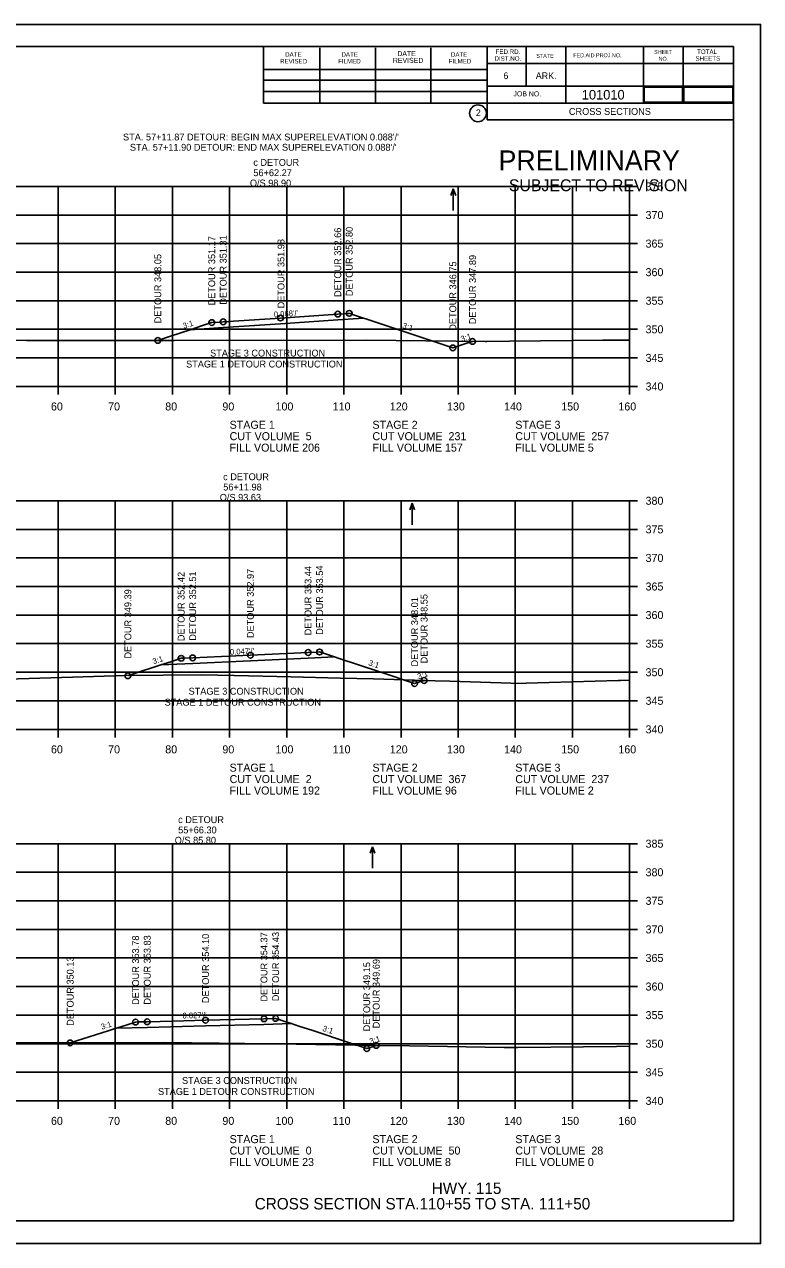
# Model space of a CAD drawing. Extents: x 1630712 to 1632516, y 782146 to 785403.
# Drawn here: x 1632387 to 1632515.9, y 784336.6 to 784550 of the extents above; entities that cross this region are included whole.
import ezdxf

# ---------------------------------------------------------------- set-up
doc = ezdxf.new("R2010")
doc.units = 0
for name, color, linetype in [('Notes', 7, 'Continuous'), ('Page Number', 7, 'Continuous'), ('R_Axis', 7, 'Continuous'), ('R_Axis Annot', 7, 'Continuous'), ('R_Border', 7, 'Continuous'), ('R_Border Notes', 7, 'Continuous'), ('R_Border Prem', 7, 'Continuous'), ('R_Detour Subgrade', 7, 'Continuous'), ('R_Detour Surface', 7, 'Continuous'), ('R_Draft', 7, 'Continuous'), ('R_Exist Surface', 7, 'Continuous'), ('R_Grid', 7, 'Continuous'), ('R_No Plot', 7, 'Continuous'), ('R_Water Annot', 7, 'Continuous'), ('R_Xsect Elev Detour', 7, 'Continuous'), ('R_Xsect Slope', 7, 'Continuous'), ('Total_Pages', 7, 'Continuous')]:
    doc.layers.add(name, color=color, linetype=linetype)

msp = doc.modelspace()

# ---------------------------------------------------------------- linework, layer by layer
at = {"layer": 'Page Number'}
msp.add_lwpolyline([(1632495.54, 784536.36), (1632502.21, 784536.36), (1632502.21, 784539), (1632495.54, 784539)], close=True, dxfattribs=at)
at = {"layer": 'R_Axis'}
for p, q in [((1632492.96, 784486.63), (1632492.96, 784521.63)), ((1632494.36, 784521.63), (1632492.96, 784521.63)), ((1632494.36, 784516.63), (1632492.96, 784516.63)), ((1632494.36, 784511.63), (1632492.96, 784511.63)), ((1632494.36, 784506.63), (1632492.96, 784506.63)), ((1632494.36, 784501.63), (1632492.96, 784501.63)), ((1632494.36, 784496.63), (1632492.96, 784496.63)), ((1632494.36, 784491.63), (1632492.96, 784491.63)), ((1632212.96, 784486.63), (1632492.96, 784486.63)), ((1632392.96, 784485.23), (1632392.96, 784486.63)), ((1632402.96, 784485.23), (1632402.96, 784486.63)), ((1632412.96, 784485.23), (1632412.96, 784486.63)), ((1632422.96, 784485.23), (1632422.96, 784486.63)), ((1632432.96, 784485.23), (1632432.96, 784486.63)), ((1632442.96, 784485.23), (1632442.96, 784486.63)), ((1632452.96, 784485.23), (1632452.96, 784486.63)), ((1632462.96, 784485.23), (1632462.96, 784486.63)), ((1632472.96, 784485.23), (1632472.96, 784486.63)), ((1632482.96, 784485.23), (1632482.96, 784486.63)), ((1632492.96, 784485.23), (1632492.96, 784486.63)), ((1632494.36, 784486.63), (1632492.96, 784486.63)), ((1632492.96, 784426.63), (1632492.96, 784466.63)), ((1632494.36, 784466.63), (1632492.96, 784466.63)), ((1632494.36, 784461.63), (1632492.96, 784461.63)), ((1632494.36, 784456.63), (1632492.96, 784456.63)), ((1632494.36, 784451.63), (1632492.96, 784451.63)), ((1632494.36, 784446.63), (1632492.96, 784446.63)), ((1632494.36, 784441.63), (1632492.96, 784441.63)), ((1632494.36, 784436.63), (1632492.96, 784436.63)), ((1632494.36, 784431.63), (1632492.96, 784431.63)), ((1632212.96, 784426.63), (1632492.96, 784426.63)), ((1632392.96, 784425.23), (1632392.96, 784426.63)), ((1632402.96, 784425.23), (1632402.96, 784426.63)), ((1632412.96, 784425.23), (1632412.96, 784426.63)), ((1632422.96, 784425.23), (1632422.96, 784426.63)), ((1632432.96, 784425.23), (1632432.96, 784426.63)), ((1632442.96, 784425.23), (1632442.96, 784426.63)), ((1632452.96, 784425.23), (1632452.96, 784426.63)), ((1632462.96, 784425.23), (1632462.96, 784426.63)), ((1632472.96, 784425.23), (1632472.96, 784426.63)), ((1632482.96, 784425.23), (1632482.96, 784426.63)), ((1632492.96, 784425.23), (1632492.96, 784426.63)), ((1632494.36, 784426.63), (1632492.96, 784426.63)), ((1632492.96, 784361.63), (1632492.96, 784406.63)), ((1632494.36, 784406.63), (1632492.96, 784406.63)), ((1632494.36, 784401.63), (1632492.96, 784401.63)), ((1632494.36, 784396.63), (1632492.96, 784396.63)), ((1632494.36, 784391.63), (1632492.96, 784391.63)), ((1632494.36, 784386.63), (1632492.96, 784386.63)), ((1632494.36, 784381.63), (1632492.96, 784381.63)), ((1632494.36, 784376.63), (1632492.96, 784376.63)), ((1632494.36, 784371.63), (1632492.96, 784371.63)), ((1632494.36, 784366.63), (1632492.96, 784366.63)), ((1632212.96, 784361.63), (1632492.96, 784361.63)), ((1632392.96, 784360.23), (1632392.96, 784361.63)), ((1632402.96, 784360.23), (1632402.96, 784361.63)), ((1632412.96, 784360.23), (1632412.96, 784361.63)), ((1632422.96, 784360.23), (1632422.96, 784361.63)), ((1632432.96, 784360.23), (1632432.96, 784361.63)), ((1632442.96, 784360.23), (1632442.96, 784361.63)), ((1632452.96, 784360.23), (1632452.96, 784361.63)), ((1632462.96, 784360.23), (1632462.96, 784361.63)), ((1632472.96, 784360.23), (1632472.96, 784361.63)), ((1632482.96, 784360.23), (1632482.96, 784361.63)), ((1632492.96, 784360.23), (1632492.96, 784361.63)), ((1632494.36, 784361.63), (1632492.96, 784361.63))]:
    msp.add_line(p, q, dxfattribs=at)
at = {"layer": 'R_Border'}
for p, q in [((1632194.96, 784546.09), (1632511.14, 784546.09)), ((1632428.88, 784536.21), (1632428.88, 784546.09)), ((1632438.74, 784536.21), (1632438.74, 784545.89)), ((1632448.5, 784536.21), (1632448.5, 784545.89)), ((1632458.18, 784536.21), (1632458.18, 784545.89)), ((1632468.04, 784546.09), (1632468.04, 784533.29)), ((1632474.88, 784546.09), (1632474.88, 784539.15)), ((1632481.82, 784546.09), (1632481.82, 784536.21)), ((1632495.4, 784546.09), (1632495.4, 784536.21)), ((1632502.34, 784546.09), (1632502.34, 784536.21)), ((1632511.14, 784340.63), (1632511.14, 784546.09)), ((1632511.14, 784543.15), (1632468.04, 784543.15)), ((1632511.14, 784543.17), (1632511.14, 784543.17)), ((1632428.88, 784542.07), (1632468.04, 784542.07)), ((1632428.88, 784540.21), (1632468.04, 784540.21)), ((1632511.14, 784539.15), (1632468.04, 784539.15)), ((1632471, 784539.15), (1632511.14, 784539.15)), ((1632428.88, 784536.21), (1632428.88, 784538.27)), ((1632428.88, 784538.27), (1632468.04, 784538.27)), ((1632511.14, 784536.21), (1632428.88, 784536.21)), ((1632468.04, 784533.29), (1632511.14, 784533.29)), ((1632511.14, 784340.63), (1632194.96, 784340.63))]:
    msp.add_line(p, q, dxfattribs=at)
msp.add_circle((1632466.43, 784534.43), 1.47, dxfattribs=at)
at = {"layer": 'R_Detour Subgrade'}
for points in [[(1632416.04, 784496.55), (1632421.84, 784496.94), (1632431.87, 784497.61), (1632441.89, 784498.29), (1632446.39, 784498.6)], [(1632410.92, 784437.9), (1632416.5, 784438.14), (1632426.6, 784438.6), (1632436.69, 784439.08), (1632441.34, 784439.3)], [(1632403.12, 784374.34), (1632408.55, 784374.47), (1632418.76, 784374.73), (1632428.98, 784375), (1632433.81, 784375.14)]]:
    msp.add_lwpolyline(points, dxfattribs=at)
at = {"layer": 'R_Detour Surface'}
for points in [[(1632410.4, 784494.68), (1632412.6, 784495.41), (1632416.04, 784496.55), (1632418.21, 784497.27), (1632419.84, 784497.81), (1632421.17, 784497.89), (1632421.84, 784497.94), (1632431.87, 784498.61), (1632431.87, 784498.61), (1632431.87, 784498.61), (1632431.87, 784498.61), (1632441.89, 784499.29), (1632443.79, 784499.42), (1632443.9, 784499.43), (1632444.46, 784499.24), (1632446.39, 784498.6), (1632446.4, 784498.6), (1632446.99, 784498.4), (1632459.74, 784494.15), (1632462.03, 784493.38), (1632464.81, 784494.3), (1632465.48, 784494.52)], [(1632405.19, 784436.03), (1632406.14, 784436.34), (1632410.92, 784437.9), (1632412.68, 784438.47), (1632414.48, 784439.06), (1632414.79, 784439.07), (1632416.5, 784439.14), (1632426.58, 784439.6), (1632426.6, 784439.6), (1632426.6, 784439.6), (1632436.69, 784440.08), (1632438.24, 784440.15), (1632438.71, 784440.17), (1632439.38, 784439.95), (1632441.34, 784439.3), (1632441.52, 784439.24), (1632441.94, 784439.1), (1632449.23, 784436.67), (1632455.34, 784434.64), (1632456.05, 784434.87), (1632457, 784435.18)], [(1632395.07, 784371.76), (1632401.72, 784373.89), (1632403.12, 784374.34), (1632403.91, 784374.59), (1632406.51, 784375.42), (1632407.14, 784375.44), (1632408.55, 784375.47), (1632413.1, 784375.59), (1632418.76, 784375.73), (1632426.44, 784375.94), (1632428.98, 784376), (1632430.71, 784376.05), (1632431.02, 784376.06), (1632433.56, 784375.22), (1632433.81, 784375.14), (1632434.38, 784374.95), (1632434.42, 784374.94), (1632435.07, 784374.72), (1632437.52, 784373.91), (1632443.75, 784371.85), (1632446.96, 784370.78), (1632447.9, 784371.08), (1632448.61, 784371.31)]]:
    msp.add_lwpolyline(points, dxfattribs=at)
at = {"layer": 'R_Exist Surface'}
for points in [[(1632383.37, 784494.78), (1632387.42, 784494.7), (1632413.31, 784494.68), (1632446.87, 784494.72), (1632467.73, 784494.5), (1632468, 784494.5), (1632471.94, 784494.54), (1632488.29, 784494.71), (1632489.38, 784494.72), (1632492.96, 784494.71)], [(1632384.07, 784435.42), (1632397.36, 784435.83), (1632404.7, 784436.03), (1632418.02, 784436.19), (1632423.79, 784436.03), (1632433.72, 784435.82), (1632442.34, 784435.58), (1632448.12, 784435.45), (1632458.93, 784435.13), (1632461.49, 784435.07), (1632474, 784434.68), (1632474.01, 784434.68), (1632474.89, 784434.7), (1632490.96, 784435.21), (1632491.36, 784435.21), (1632492.96, 784435.26)], [(1632384.31, 784371.85), (1632396.09, 784371.76), (1632399.09, 784371.78), (1632411.51, 784371.85), (1632421.14, 784371.7), (1632434.6, 784371.54), (1632448.37, 784371.32), (1632454.46, 784371.24), (1632470.99, 784370.95), (1632473.4, 784370.95), (1632490.7, 784371.14), (1632492.96, 784371.18)]]:
    msp.add_lwpolyline(points, dxfattribs=at)
at = {"layer": 'R_Grid'}
for p, q in [((1632212.96, 784521.63), (1632492.96, 784521.63)), ((1632392.96, 784486.63), (1632392.96, 784521.63)), ((1632402.96, 784486.63), (1632402.96, 784521.63)), ((1632412.96, 784486.63), (1632412.96, 784521.63)), ((1632422.96, 784486.63), (1632422.96, 784521.63)), ((1632432.96, 784486.63), (1632432.96, 784521.63)), ((1632442.96, 784486.63), (1632442.96, 784521.63)), ((1632452.96, 784486.63), (1632452.96, 784521.63)), ((1632462.96, 784486.63), (1632462.96, 784521.63)), ((1632472.96, 784486.63), (1632472.96, 784521.63)), ((1632482.96, 784486.63), (1632482.96, 784521.63)), ((1632492.96, 784486.63), (1632492.96, 784521.63)), ((1632212.96, 784516.63), (1632492.96, 784516.63)), ((1632212.96, 784511.63), (1632492.96, 784511.63)), ((1632212.96, 784506.63), (1632492.96, 784506.63)), ((1632212.96, 784501.63), (1632492.96, 784501.63)), ((1632212.96, 784496.63), (1632492.96, 784496.63)), ((1632212.96, 784491.63), (1632492.96, 784491.63)), ((1632212.96, 784486.63), (1632492.96, 784486.63)), ((1632212.96, 784466.63), (1632492.96, 784466.63)), ((1632392.96, 784426.63), (1632392.96, 784466.63)), ((1632402.96, 784426.63), (1632402.96, 784466.63)), ((1632412.96, 784426.63), (1632412.96, 784466.63)), ((1632422.96, 784426.63), (1632422.96, 784466.63)), ((1632432.96, 784426.63), (1632432.96, 784466.63)), ((1632442.96, 784426.63), (1632442.96, 784466.63)), ((1632452.96, 784426.63), (1632452.96, 784466.63)), ((1632462.96, 784426.63), (1632462.96, 784466.63)), ((1632472.96, 784426.63), (1632472.96, 784466.63)), ((1632482.96, 784426.63), (1632482.96, 784466.63)), ((1632492.96, 784426.63), (1632492.96, 784466.63)), ((1632212.96, 784461.63), (1632492.96, 784461.63)), ((1632212.96, 784456.63), (1632492.96, 784456.63)), ((1632212.96, 784451.63), (1632492.96, 784451.63)), ((1632212.96, 784446.63), (1632492.96, 784446.63)), ((1632212.96, 784441.63), (1632492.96, 784441.63)), ((1632212.96, 784436.63), (1632492.96, 784436.63)), ((1632212.96, 784431.63), (1632492.96, 784431.63)), ((1632212.96, 784426.63), (1632492.96, 784426.63)), ((1632212.96, 784406.63), (1632492.96, 784406.63)), ((1632392.96, 784361.63), (1632392.96, 784406.63)), ((1632402.96, 784361.63), (1632402.96, 784406.63)), ((1632412.96, 784361.63), (1632412.96, 784406.63)), ((1632422.96, 784361.63), (1632422.96, 784406.63)), ((1632432.96, 784361.63), (1632432.96, 784406.63)), ((1632442.96, 784361.63), (1632442.96, 784406.63)), ((1632452.96, 784361.63), (1632452.96, 784406.63)), ((1632462.96, 784361.63), (1632462.96, 784406.63)), ((1632472.96, 784361.63), (1632472.96, 784406.63)), ((1632482.96, 784361.63), (1632482.96, 784406.63)), ((1632492.96, 784361.63), (1632492.96, 784406.63)), ((1632212.96, 784401.63), (1632492.96, 784401.63)), ((1632212.96, 784396.63), (1632492.96, 784396.63)), ((1632212.96, 784391.63), (1632492.96, 784391.63)), ((1632212.96, 784386.63), (1632492.96, 784386.63)), ((1632212.96, 784381.63), (1632492.96, 784381.63)), ((1632212.96, 784376.63), (1632492.96, 784376.63)), ((1632212.96, 784371.63), (1632492.96, 784371.63)), ((1632212.96, 784366.63), (1632492.96, 784366.63)), ((1632212.96, 784361.63), (1632492.96, 784361.63))]:
    msp.add_line(p, q, dxfattribs=at)
at = {"layer": 'R_No Plot'}
for p, q in [((1632182.56, 784549.99), (1632515.9, 784549.99)), ((1632182.56, 784336.65), (1632515.9, 784336.65))]:
    msp.add_line(p, q, dxfattribs=at)
msp.add_lwpolyline([(1632182.56, 784549.99), (1632515.9, 784549.99), (1632515.9, 784336.65), (1632182.56, 784336.65)], close=True, dxfattribs=at)
for centre in [(1632419.84, 784497.81), (1632421.84, 784497.94), (1632431.87, 784498.61), (1632441.89, 784499.29), (1632443.9, 784499.43), (1632410.4, 784494.68), (1632462.03, 784493.38), (1632465.48, 784494.52), (1632436.69, 784440.08), (1632438.71, 784440.17), (1632414.48, 784439.06), (1632416.5, 784439.14), (1632426.6, 784439.6), (1632405.16, 784436.02), (1632455.34, 784434.64), (1632457, 784435.18), (1632418.76, 784375.73), (1632428.98, 784376), (1632431.02, 784376.06), (1632406.51, 784375.42), (1632408.55, 784375.47), (1632395.07, 784371.76), (1632446.96, 784370.78), (1632448.62, 784371.32)]:
    msp.add_circle(centre, 0.5, dxfattribs=at)
at = {"layer": 'R_Water Annot'}
for p, q in [((1632462.11, 784521.2), (1632461.69, 784520.05)), ((1632462.11, 784517.43), (1632462.11, 784521.2)), ((1632462.11, 784521.2), (1632462.53, 784520.05)), ((1632454.91, 784466.2), (1632454.49, 784465.05)), ((1632454.91, 784462.43), (1632454.91, 784466.2)), ((1632454.91, 784466.2), (1632455.33, 784465.05)), ((1632447.97, 784406.1), (1632447.55, 784404.95)), ((1632447.97, 784402.33), (1632447.97, 784406.1)), ((1632447.97, 784406.1), (1632448.39, 784404.95))]:
    msp.add_line(p, q, dxfattribs=at)
at = {"layer": 'Total_Pages'}
msp.add_lwpolyline([(1632502.44, 784536.36), (1632511.05, 784536.36), (1632511.05, 784539), (1632502.44, 784539)], close=True, dxfattribs=at)

# ---------------------------------------------------------------- texts
at = {"layer": 'Notes'}
for s, p in [("STA. 57+11.87 DETOUR: BEGIN MAX SUPERELEVATION 0.088'/'", (1632404.31, 784529.68)), ("STA. 57+11.90 DETOUR: END MAX SUPERELEVATION 0.088'/'", (1632405.51, 784527.88)), ('c DETOUR', (1632427.11, 784525.23)), ('56+62.27', (1632427.12, 784523.43)), ('O/S 98.90', (1632426.51, 784521.63)), ('STAGE 3 CONSTRUCTION', (1632419.55, 784491.87)), ('STAGE 1 DETOUR CONSTRUCTION', (1632415.35, 784489.95)), ('c DETOUR', (1632421.83, 784470.23)), ('56+11.98', (1632421.85, 784468.43)), ('O/S 93.63', (1632421.24, 784466.63)), ('STAGE 3 CONSTRUCTION', (1632415.78, 784432.7)), ('STAGE 1 DETOUR CONSTRUCTION', (1632411.58, 784430.78)), ('c DETOUR', (1632413.95, 784410.23)), ('55+66.30', (1632413.96, 784408.43)), ('O/S 85.80', (1632413.36, 784406.63)), ('STAGE 3 CONSTRUCTION', (1632414.63, 784364.59)), ('STAGE 1 DETOUR CONSTRUCTION', (1632410.43, 784362.67))]:
    msp.add_text(s, height=1.2, dxfattribs=at).set_placement(p)
at = {"layer": 'R_Axis Annot'}
for s, p in [('375', (1632495.76, 784520.93)), ('370', (1632495.76, 784515.93)), ('365', (1632495.76, 784510.93)), ('360', (1632495.76, 784505.93)), ('355', (1632495.76, 784500.93)), ('350', (1632495.76, 784495.93)), ('345', (1632495.76, 784490.93)), ('340', (1632495.76, 784485.93)), ('60', (1632391.7, 784482.43)), ('70', (1632401.7, 784482.43)), ('80', (1632411.7, 784482.43)), ('90', (1632421.7, 784482.43)), ('100', (1632431, 784482.43)), ('110', (1632441, 784482.43)), ('120', (1632451, 784482.43)), ('130', (1632461, 784482.43)), ('140', (1632471, 784482.43)), ('150', (1632481, 784482.43)), ('160', (1632491, 784482.43)), ('STAGE 1', (1632422.96, 784479.23)), ('CUT VOLUME  5', (1632422.96, 784477.23)), ('STAGE 2', (1632447.96, 784479.23)), ('CUT VOLUME  231', (1632447.96, 784477.23)), ('STAGE 3', (1632472.96, 784479.23)), ('CUT VOLUME  257', (1632472.96, 784477.23)), ('FILL VOLUME 206', (1632422.96, 784475.23)), ('FILL VOLUME 157', (1632447.96, 784475.23)), ('FILL VOLUME 5', (1632472.96, 784475.23)), ('380', (1632495.76, 784465.93)), ('375', (1632495.76, 784460.93)), ('370', (1632495.76, 784455.93)), ('365', (1632495.76, 784450.93)), ('360', (1632495.76, 784445.93)), ('355', (1632495.76, 784440.93)), ('350', (1632495.76, 784435.93)), ('345', (1632495.76, 784430.93)), ('340', (1632495.76, 784425.93)), ('60', (1632391.7, 784422.43)), ('70', (1632401.7, 784422.43)), ('80', (1632411.7, 784422.43)), ('90', (1632421.7, 784422.43)), ('100', (1632431, 784422.43)), ('110', (1632441, 784422.43)), ('120', (1632451, 784422.43)), ('130', (1632461, 784422.43)), ('140', (1632471, 784422.43)), ('150', (1632481, 784422.43)), ('160', (1632491, 784422.43)), ('STAGE 1', (1632422.96, 784419.23)), ('STAGE 2', (1632447.96, 784419.23)), ('STAGE 3', (1632472.96, 784419.23)), ('CUT VOLUME  2', (1632422.96, 784417.23)), ('CUT VOLUME  367', (1632447.96, 784417.23)), ('CUT VOLUME  237', (1632472.96, 784417.23)), ('FILL VOLUME 192', (1632422.96, 784415.23)), ('FILL VOLUME 96', (1632447.96, 784415.23)), ('FILL VOLUME 2', (1632472.96, 784415.23)), ('385', (1632495.76, 784405.93)), ('380', (1632495.76, 784400.93)), ('375', (1632495.76, 784395.93)), ('370', (1632495.76, 784390.93)), ('365', (1632495.76, 784385.93)), ('360', (1632495.76, 784380.93)), ('355', (1632495.76, 784375.93)), ('350', (1632495.76, 784370.93)), ('345', (1632495.76, 784365.93)), ('340', (1632495.76, 784360.93)), ('60', (1632391.7, 784357.43)), ('70', (1632401.7, 784357.43)), ('80', (1632411.7, 784357.43)), ('90', (1632421.7, 784357.43)), ('100', (1632431, 784357.43)), ('110', (1632441, 784357.43)), ('120', (1632451, 784357.43)), ('130', (1632461, 784357.43)), ('140', (1632471, 784357.43)), ('150', (1632481, 784357.43)), ('160', (1632491, 784357.43)), ('STAGE 1', (1632422.96, 784354.23)), ('STAGE 2', (1632447.96, 784354.23)), ('STAGE 3', (1632472.96, 784354.23)), ('CUT VOLUME  0', (1632422.96, 784352.23)), ('CUT VOLUME  50', (1632447.96, 784352.23)), ('CUT VOLUME  28', (1632472.96, 784352.23)), ('FILL VOLUME 23', (1632422.96, 784350.23)), ('FILL VOLUME 8', (1632447.96, 784350.23)), ('FILL VOLUME 0', (1632472.96, 784350.23))]:
    msp.add_text(s, height=1.4, dxfattribs=at).set_placement(p)
at = {"layer": 'R_Border'}
for s, height, p in [('DATE', 0.782, (1632432.68, 784544.33)), ('DATE', 0.782, (1632442.54, 784544.33)), ('DATE', 0.879, (1632452.32, 784544.43)), ('DATE', 0.782, (1632461.7, 784544.33)), ('FED.RD.', 0.782, (1632469.52, 784544.81)), ('STATE', 0.684, (1632476.64, 784544.13)), ('FED.AID PROJ.NO.', 0.684, (1632483.1, 784544.23)), ('SHEET', 0.684, (1632497.26, 784544.81)), ('TOTAL', 0.782, (1632504.78, 784544.81)), ('REVISED', 0.782, (1632431.8, 784543.15)), ('FILMED', 0.782, (1632441.96, 784543.15)), ('REVISED', 0.879, (1632451.54, 784543.25)), ('FILMED', 0.782, (1632461.3, 784543.15)), ('DIST.NO.', 0.782, (1632469.32, 784543.63)), ('NO.', 0.684, (1632498.04, 784543.63)), ('SHEETS', 0.782, (1632504.5, 784543.63)), ('6', 1.17, (1632470.88, 784540.41)), ('ARK.', 1.172, (1632476.54, 784540.41)), ('JOB NO.', 0.879, (1632472.64, 784537.39)), ('2', 1.17, (1632466.05, 784533.94))]:
    msp.add_text(s, height=height, rotation=360, dxfattribs=at).set_placement(p)
at = {"layer": 'R_Border Notes'}
for s, height, p in [('101010', 1.68, (1632484.6, 784536.84)), ('CROSS SECTIONS', 1.2, (1632482.34, 784534.15))]:
    msp.add_text(s, height=height, dxfattribs=at).set_placement(p)
at = {"layer": 'R_Border Prem'}
for s, height, p in [('PRELIMINARY', 3.5, (1632470.03, 784524.43)), ('SUBJECT TO REVISION', 2.0751, (1632471.84, 784520.8))]:
    msp.add_text(s, height=height, rotation=360, dxfattribs=at).set_placement(p)
at = {"layer": 'R_Draft'}
for s, p in [('HWY. 115', (1632458.34, 784345.34)), ('CROSS SECTION STA.110+55 TO STA. 111+50', (1632427.36, 784342.63))]:
    msp.add_text(s, height=2, dxfattribs=at).set_placement(p)
at = {"layer": 'R_Xsect Elev Detour'}
for s, p in [('DETOUR 351.17', (1632420.44, 784500.81)), ('DETOUR 351.31', (1632422.44, 784500.94)), ('DETOUR 352.66', (1632442.49, 784502.29)), ('DETOUR 352.80', (1632444.5, 784502.43)), ('DETOUR 351.98', (1632432.56, 784500.3)), ('DETOUR 348.05', (1632411, 784497.68)), ('DETOUR 347.89', (1632466.08, 784497.52)), ('DETOUR 346.75', (1632462.63, 784496.38)), ('DETOUR 353.44', (1632437.29, 784443.08)), ('DETOUR 353.54', (1632439.31, 784443.17)), ('DETOUR 352.42', (1632415.08, 784442.06)), ('DETOUR 352.51', (1632417.1, 784442.14)), ('DETOUR 352.97', (1632427.2, 784442.6)), ('DETOUR 349.39', (1632405.76, 784439.02)), ('DETOUR 348.01', (1632455.94, 784437.64)), ('DETOUR 348.55', (1632457.6, 784438.18)), ('DETOUR 353.78', (1632407.11, 784378.42)), ('DETOUR 353.83', (1632409.15, 784378.47)), ('DETOUR 354.10', (1632419.36, 784378.73)), ('DETOUR 354.37', (1632429.58, 784379)), ('DETOUR 354.43', (1632431.62, 784379.06)), ('DETOUR 350.13', (1632395.67, 784374.76)), ('DETOUR 349.15', (1632447.56, 784373.78)), ('DETOUR 349.69', (1632449.22, 784374.32))]:
    msp.add_text(s, height=1.2, rotation=90, dxfattribs=at).set_placement(p)
at = {"layer": 'R_Xsect Slope'}
for s, rotation, p in [("0.068'/'", 3.8884, (1632430.74, 784498.72)), ('3:1', 18.3084, (1632414.96, 784496.72)), ('3:1', 341.5589, (1632453.12, 784496.88)), ('3:1', 18.2685, (1632463.6, 784494.43)), ("0.047'/'", 2.685, (1632423.04, 784439.67)), ('3:1', 18.0457, (1632409.66, 784438.01)), ('3:1', 341.6042, (1632447.18, 784437.88)), ('3:1', 18.047, (1632456.01, 784435.39)), ("0.027'/'", 1.5522, (1632414.73, 784376.03)), ('3:1', 17.7265, (1632400.64, 784374.07)), ('3:1', 341.6883, (1632439.15, 784373.9)), ('3:1', 17.8137, (1632447.64, 784371.53))]:
    msp.add_text(s, height=1, rotation=rotation, dxfattribs=at).set_placement(p)

doc.saveas('drawing.dxf')
